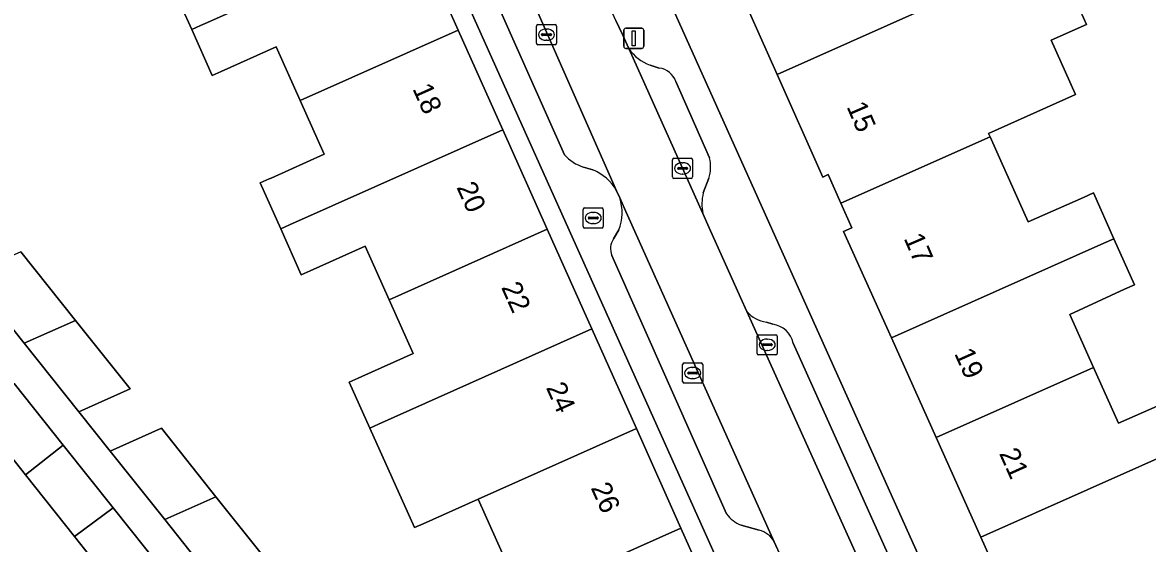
# Model space of a CAD drawing. Extents: x 163147 to 163550, y 380933 to 381639.
# Drawn here: x 163249.5 to 163305.4, y 381171.6 to 381197.5 of the extents above; entities that cross this region are included whole.
import ezdxf

# ---------------------------------------------------------------- set-up
doc = ezdxf.new("R2010")
doc.units = 0
for name, color, linetype in [('IMGEO_Brandkraan', 7, 'Continuous'), ('IMGEO_Erf', 7, 'Continuous'), ('IMGEO_Kolk', 7, 'Continuous'), ('IMGEO_Lichtmast', 7, 'Continuous'), ('IMGEO_Pand', 7, 'Continuous'), ('IMGEO_Pand_nummerreeks', 7, 'Continuous'), ('IMGEO_Parkeervlak_open', 7, 'Continuous'), ('IMGEO_Rijbaan_lokaal_open', 7, 'Continuous'), ('IMGEO_Voetpad_open', 7, 'Continuous')]:
    doc.layers.add(name, color=color, linetype=linetype)

msp = doc.modelspace()

# ---------------------------------------------------------------- linework, layer by layer
at = {"layer": 'IMGEO_Brandkraan'}
for p, q in [((163277.371, 381187.358), (163277.371, 381188.21)), ((163277.446, 381188.284), (163278.298, 381188.284)), ((163278.372, 381188.21), (163278.372, 381187.358)), ((163277.63, 381187.778), (163277.63, 381187.79)), ((163278.068, 381187.741), (163277.67, 381187.741)), ((163277.673, 381187.827), (163278.071, 381187.827)), ((163277.859, 381188.064), (163277.884, 381188.064)), ((163278.114, 381187.79), (163278.114, 381187.778)), ((163278.298, 381187.284), (163277.446, 381187.284)), ((163277.882, 381187.504), (163277.857, 381187.504))]:
    msp.add_line(p, q, dxfattribs=at)
for points in [[(163277.371, 381187.358), (163277.371, 381188.21)], [(163277.446, 381188.284), (163278.298, 381188.284)], [(163278.372, 381188.21), (163278.372, 381187.358)], [(163278.298, 381187.284), (163277.446, 381187.284)]]:
    msp.add_lwpolyline(points, dxfattribs=at)
for centre, radius, start, end in [((163277.448, 381188.208), 0.0765, 91.552, 178.448), ((163277.448, 381188.208), 0.0765, 91.552, 178.448), ((163278.296, 381188.208), 0.0765, 1.552, 88.448), ((163278.296, 381188.208), 0.0765, 1.552, 88.448), ((163277.67, 381187.787), 0.0403, 85.8775, 175.7526), ((163277.667, 381187.777), 0.0366, 178.938, 274.7102), ((163278.071, 381187.784), 0.043, 264.8664, 352.4533), ((163278.075, 381187.789), 0.0386, 1.7309, 96.639), ((163277.448, 381187.36), 0.0765, 181.552, 268.448), ((163277.448, 381187.36), 0.0765, 181.552, 268.448), ((163278.296, 381187.36), 0.0765, 271.552, 358.448), ((163278.296, 381187.36), 0.0765, 271.552, 358.448)]:
    msp.add_arc(centre, radius, start, end, dxfattribs=at)
for centre, major_axis, ratio, start_param, end_param in [((163277.858, 381187.784), (-0.387, 0.002), 0.722429, 4.712389, 7.853982), ((163277.883, 381187.784), (-0.39, 0.002), 0.717154, 1.570796, 4.712389)]:
    msp.add_ellipse(centre, major_axis=major_axis, ratio=ratio, start_param=start_param, end_param=end_param, dxfattribs=at)
at = {"layer": 'IMGEO_Erf'}
for points in [[(163270.156, 381224.203), (163305.202, 381146.131), (163304.985, 381145.89), (163307.687, 381144.941)], [(163249.445, 381186.105), (163252.159, 381182.695), (163254.871, 381179.287), (163252.323, 381178.149), (163253.099, 381177.174), (163253.874, 381176.2), (163256.422, 381177.338), (163259.133, 381173.931), (163261.845, 381170.523), (163259.298, 381169.386), (163260.074, 381168.411), (163260.866, 381167.416), (163263.413, 381168.553), (163266.107, 381165.167), (163268.685, 381161.928), (163266.571, 381160.249), (163267.347, 381159.274), (163282.659, 381139.767), (163292.918, 381150.971), (163261.531, 381220.959)], [(163268.958, 381202.078), (163271.17, 381197.125), (163273.381, 381192.174), (163275.592, 381187.222), (163277.802, 381182.271), (163280.014, 381177.318), (163282.224, 381172.367), (163284.436, 381167.414)], [(163300.743, 381201.067), (163302.37, 381197.403), (163300.616, 381196.616), (163301.823, 381193.924), (163297.507, 381191.987), (163297.586, 381191.811), (163298.121, 381190.618), (163299.481, 381187.587), (163302.222, 381188.807), (163302.722, 381189.029), (163303.738, 381186.745), (163304.755, 381184.461), (163304.269, 381184.245), (163301.543, 381182.991), (163302.725, 381180.356), (163303.971, 381177.58), (163306.712, 381178.8)], [(163264.607, 381120.389), (163281.562, 381138.569), (163278.275, 381142.629), (163276.479, 381141.205), (163274.017, 381144.311), (163273.373, 381145.124), (163271.555, 381147.417), (163269.093, 381150.523), (163266.667, 381153.583), (163264.241, 381156.644), (163261.814, 381159.705), (163259.391, 381162.762), (163256.967, 381165.819), (163254.544, 381168.876), (163252.108, 381171.949), (163249.676, 381175.016), (163247.243, 381178.086), (163244.815, 381181.148), (163242.387, 381184.211), (163239.96, 381187.273), (163237.536, 381190.33), (163235.112, 381193.388), (163232.688, 381196.445), (163230.267, 381199.5)], [(163273.352, 381171.141), (163272.16, 381173.81), (163269.42, 381172.587), (163268.988, 381172.394), (163266.775, 381177.345), (163265.755, 381179.628), (163266.19, 381179.822), (163266.375, 381179.904), (163268.93, 381181.045), (163267.738, 381183.714), (163266.546, 381186.383), (163263.807, 381185.16), (163263.37, 381184.965), (163262.35, 381187.246), (163261.33, 381189.529), (163261.769, 381189.725), (163261.872, 381189.771), (163264.508, 381190.949), (163263.316, 381193.617), (163262.124, 381196.287), (163259.385, 381195.063), (163258.945, 381194.866), (163257.925, 381197.149), (163256.904, 381199.431)], [(163306.015, 381152.115), (163303.793, 381157.068), (163301.571, 381162.02), (163299.349, 381166.972), (163297.126, 381171.926), (163294.905, 381176.877), (163292.684, 381181.828), (163290.312, 381187.114), (163290.722, 381187.298), (163290.18, 381188.516), (163289.547, 381189.939), (163289.272, 381189.817), (163287.005, 381194.915), (163284.8, 381199.874)]]:
    msp.add_lwpolyline(points, dxfattribs=at)
at = {"layer": 'IMGEO_Kolk'}
for p, q in [((163275.05, 381196.471), (163275.05, 381197.323)), ((163275.125, 381197.397), (163275.977, 381197.397)), ((163275.538, 381197.177), (163275.563, 381197.177)), ((163276.051, 381197.323), (163276.051, 381196.471)), ((163275.309, 381196.891), (163275.309, 381196.903)), ((163275.747, 381196.854), (163275.349, 381196.854)), ((163275.352, 381196.94), (163275.75, 381196.94)), ((163275.561, 381196.617), (163275.536, 381196.617)), ((163275.793, 381196.903), (163275.793, 381196.891)), ((163275.977, 381196.397), (163275.125, 381196.397)), ((163281.81, 381189.824), (163281.81, 381190.676)), ((163281.885, 381190.75), (163282.737, 381190.75)), ((163282.298, 381190.53), (163282.323, 381190.53)), ((163282.811, 381190.676), (163282.811, 381189.824)), ((163282.069, 381190.244), (163282.069, 381190.256)), ((163282.507, 381190.207), (163282.109, 381190.207)), ((163282.112, 381190.293), (163282.51, 381190.293)), ((163282.321, 381189.97), (163282.296, 381189.97)), ((163282.553, 381190.256), (163282.553, 381190.244)), ((163282.737, 381189.75), (163281.885, 381189.75)), ((163286.015, 381181.057), (163286.015, 381181.909)), ((163286.09, 381181.983), (163286.942, 381181.983)), ((163286.274, 381181.477), (163286.274, 381181.489)), ((163286.317, 381181.526), (163286.715, 381181.526)), ((163286.503, 381181.763), (163286.528, 381181.763)), ((163286.758, 381181.489), (163286.758, 381181.477)), ((163287.016, 381181.909), (163287.016, 381181.057)), ((163286.942, 381180.983), (163286.09, 381180.983)), ((163286.712, 381181.44), (163286.314, 381181.44)), ((163286.526, 381181.203), (163286.501, 381181.203)), ((163282.313, 381179.653), (163282.313, 381180.505)), ((163282.388, 381180.579), (163283.24, 381180.579)), ((163283.314, 381180.505), (163283.314, 381179.653)), ((163282.572, 381180.073), (163282.572, 381180.085)), ((163283.01, 381180.036), (163282.612, 381180.036)), ((163282.615, 381180.122), (163283.013, 381180.122)), ((163282.801, 381180.359), (163282.826, 381180.359)), ((163283.056, 381180.085), (163283.056, 381180.073)), ((163283.24, 381179.579), (163282.388, 381179.579)), ((163282.824, 381179.799), (163282.799, 381179.799))]:
    msp.add_line(p, q, dxfattribs=at)
for points in [[(163275.05, 381196.471), (163275.05, 381197.323)], [(163275.125, 381197.397), (163275.977, 381197.397)], [(163276.051, 381197.323), (163276.051, 381196.471)], [(163275.977, 381196.397), (163275.125, 381196.397)], [(163281.81, 381189.824), (163281.81, 381190.676)], [(163281.885, 381190.75), (163282.737, 381190.75)], [(163282.811, 381190.676), (163282.811, 381189.824)], [(163282.737, 381189.75), (163281.885, 381189.75)], [(163286.015, 381181.057), (163286.015, 381181.909)], [(163286.09, 381181.983), (163286.942, 381181.983)], [(163287.016, 381181.909), (163287.016, 381181.057)], [(163286.942, 381180.983), (163286.09, 381180.983)], [(163282.313, 381179.653), (163282.313, 381180.505)], [(163282.388, 381180.579), (163283.24, 381180.579)], [(163283.314, 381180.505), (163283.314, 381179.653)], [(163283.24, 381179.579), (163282.388, 381179.579)]]:
    msp.add_lwpolyline(points, dxfattribs=at)
for centre, radius, start, end in [((163275.127, 381197.321), 0.0765, 91.552, 178.448), ((163275.127, 381197.321), 0.0765, 91.552, 178.448), ((163275.975, 381197.321), 0.0765, 1.552, 88.448), ((163275.975, 381197.321), 0.0765, 1.552, 88.448), ((163275.349, 381196.9), 0.0403, 85.8775, 175.7526), ((163275.346, 381196.89), 0.0366, 178.938, 274.7102), ((163275.75, 381196.897), 0.043, 264.8664, 352.4533), ((163275.754, 381196.902), 0.0386, 1.7309, 96.639), ((163275.127, 381196.473), 0.0765, 181.552, 268.448), ((163275.127, 381196.473), 0.0765, 181.552, 268.448), ((163275.975, 381196.473), 0.0765, 271.552, 358.448), ((163275.975, 381196.473), 0.0765, 271.552, 358.448), ((163281.887, 381190.674), 0.0765, 91.552, 178.448), ((163281.887, 381190.674), 0.0765, 91.552, 178.448), ((163282.735, 381190.674), 0.0765, 1.552, 88.448), ((163282.735, 381190.674), 0.0765, 1.552, 88.448), ((163282.109, 381190.253), 0.0403, 85.8775, 175.7526), ((163282.106, 381190.243), 0.0366, 178.938, 274.7102), ((163282.51, 381190.25), 0.043, 264.8664, 352.4533), ((163282.514, 381190.255), 0.0386, 1.7309, 96.639), ((163281.887, 381189.826), 0.0765, 181.552, 268.448), ((163281.887, 381189.826), 0.0765, 181.552, 268.448), ((163282.735, 381189.826), 0.0765, 271.552, 358.448), ((163282.735, 381189.826), 0.0765, 271.552, 358.448), ((163286.092, 381181.907), 0.0765, 91.552, 178.448), ((163286.092, 381181.907), 0.0765, 91.552, 178.448), ((163286.314, 381181.486), 0.0403, 85.8775, 175.7526), ((163286.719, 381181.488), 0.0386, 1.7309, 96.639), ((163286.94, 381181.907), 0.0765, 1.552, 88.448), ((163286.94, 381181.907), 0.0765, 1.552, 88.448), ((163286.092, 381181.059), 0.0765, 181.552, 268.448), ((163286.092, 381181.059), 0.0765, 181.552, 268.448), ((163286.311, 381181.476), 0.0366, 178.938, 274.7102), ((163286.715, 381181.483), 0.043, 264.8664, 352.4533), ((163286.94, 381181.059), 0.0765, 271.552, 358.448), ((163286.94, 381181.059), 0.0765, 271.552, 358.448), ((163282.39, 381180.503), 0.0765, 91.552, 178.448), ((163282.39, 381180.503), 0.0765, 91.552, 178.448), ((163283.238, 381180.503), 0.0765, 1.552, 88.448), ((163283.238, 381180.503), 0.0765, 1.552, 88.448), ((163282.612, 381180.082), 0.0403, 85.8775, 175.7526), ((163282.609, 381180.072), 0.0366, 178.938, 274.7102), ((163283.013, 381180.079), 0.043, 264.8664, 352.4533), ((163283.017, 381180.084), 0.0386, 1.7309, 96.639), ((163282.39, 381179.655), 0.0765, 181.552, 268.448), ((163282.39, 381179.655), 0.0765, 181.552, 268.448), ((163283.238, 381179.655), 0.0765, 271.552, 358.448), ((163283.238, 381179.655), 0.0765, 271.552, 358.448)]:
    msp.add_arc(centre, radius, start, end, dxfattribs=at)
for centre, major_axis, ratio, start_param, end_param in [((163275.537, 381196.897), (-0.387, 0.002), 0.722429, 4.712389, 7.853982), ((163275.562, 381196.897), (-0.39, 0.002), 0.717154, 1.570796, 4.712389), ((163282.297, 381190.25), (-0.387, 0.002), 0.722429, 4.712389, 7.853982), ((163282.322, 381190.25), (-0.39, 0.002), 0.717154, 1.570796, 4.712389), ((163286.502, 381181.483), (-0.387, 0.002), 0.722429, 4.712389, 7.853982), ((163286.527, 381181.483), (-0.39, 0.002), 0.717154, 1.570796, 4.712389), ((163282.8, 381180.079), (-0.387, 0.002), 0.722429, 4.712389, 7.853982), ((163282.825, 381180.079), (-0.39, 0.002), 0.717154, 1.570796, 4.712389)]:
    msp.add_ellipse(centre, major_axis=major_axis, ratio=ratio, start_param=start_param, end_param=end_param, dxfattribs=at)
at = {"layer": 'IMGEO_Lichtmast'}
for p, q in [((163279.489, 381197.217), (163280.279, 381197.217)), ((163280.279, 381197.217), (163279.489, 381197.217)), ((163279.389, 381196.317), (163279.389, 381197.117)), ((163279.389, 381197.117), (163279.389, 381196.317)), ((163280.379, 381197.117), (163280.379, 381196.317)), ((163280.379, 381196.317), (163280.379, 381197.117)), ((163280.279, 381196.217), (163279.489, 381196.217)), ((163279.489, 381196.217), (163280.279, 381196.217))]:
    msp.add_line(p, q, dxfattribs=at)
msp.add_lwpolyline([(163279.809, 381197.092), (163279.959, 381197.092), (163279.959, 381196.342), (163279.809, 381196.342), (163279.809, 381197.092)], dxfattribs=at)
for centre, start, end in [((163279.489, 381197.117), 90, 180), ((163279.489, 381197.117), 90, 180), ((163280.279, 381197.117), 0, 90), ((163280.279, 381197.117), 360, 90), ((163279.489, 381196.317), 180, 270), ((163279.489, 381196.317), 180, 270), ((163280.279, 381196.317), 270, 0), ((163280.279, 381196.317), 270, 0)]:
    msp.add_arc(centre, 0.1, start, end, dxfattribs=at)
at = {"layer": 'IMGEO_Pand'}
for points in [[(163266.748, 381207.029), (163258.894, 381203.521), (163260.086, 381200.852), (163257.526, 381199.709), (163257.347, 381199.629), (163256.904, 381199.431), (163257.925, 381197.149), (163258.366, 381197.346), (163258.603, 381197.452), (163268.958, 381202.078)], [(163297.934, 381199.81), (163296.92, 381202.094), (163293.795, 381200.695), (163292.616, 381203.351), (163284.8, 381199.874), (163287.005, 381194.915)], [(163268.958, 381202.078), (163258.603, 381197.452), (163258.366, 381197.346), (163257.925, 381197.149), (163258.945, 381194.866), (163259.385, 381195.063), (163262.124, 381196.287), (163263.316, 381193.617), (163271.17, 381197.125)], [(163290.18, 381188.516), (163297.586, 381191.811), (163297.507, 381191.987), (163301.823, 381193.924), (163300.616, 381196.616), (163302.37, 381197.403), (163300.743, 381201.067), (163297.934, 381199.81), (163287.005, 381194.915), (163289.272, 381189.817), (163289.547, 381189.939)], [(163271.17, 381197.125), (163263.316, 381193.617), (163264.508, 381190.949), (163261.872, 381189.771), (163261.769, 381189.725), (163261.33, 381189.529), (163262.35, 381187.246), (163262.788, 381187.442), (163273.381, 381192.174)], [(163273.381, 381192.174), (163262.788, 381187.442), (163262.35, 381187.246), (163263.37, 381184.965), (163263.807, 381185.16), (163266.546, 381186.383), (163267.738, 381183.714), (163275.592, 381187.222)], [(163298.121, 381190.618), (163297.586, 381191.811), (163290.18, 381188.516), (163290.722, 381187.298), (163290.312, 381187.114), (163292.684, 381181.828), (163303.245, 381186.526), (163303.738, 381186.745), (163302.722, 381189.029), (163302.222, 381188.807), (163299.481, 381187.587)], [(163275.592, 381187.222), (163267.738, 381183.714), (163268.93, 381181.045), (163266.375, 381179.904), (163266.19, 381179.822), (163265.755, 381179.628), (163266.775, 381177.345), (163267.21, 381177.539), (163277.802, 381182.271)], [(163301.543, 381182.991), (163304.269, 381184.245), (163304.755, 381184.461), (163303.738, 381186.745), (163303.245, 381186.526), (163292.684, 381181.828), (163294.905, 381176.877), (163302.725, 381180.356)], [(163246.895, 381184.967), (163249.61, 381181.556), (163252.159, 381182.695), (163249.445, 381186.105)], [(163252.159, 381182.695), (163249.61, 381181.556), (163252.323, 381178.149), (163254.871, 381179.287)], [(163280.014, 381177.318), (163277.802, 381182.271), (163267.21, 381177.539), (163266.775, 381177.345), (163268.988, 381172.394), (163269.42, 381172.587), (163272.16, 381173.81)], [(163308.15, 381176.83), (163307.181, 381179.008), (163306.712, 381178.8), (163303.971, 381177.58), (163302.725, 381180.356), (163294.905, 381176.877), (163297.126, 381171.926), (163307.688, 381176.624)], [(163247.243, 381178.086), (163249.676, 381175.016), (163251.545, 381176.497), (163249.108, 381179.565)], [(163253.874, 381176.2), (163256.586, 381172.793), (163259.133, 381173.931), (163256.422, 381177.338)], [(163280.014, 381177.318), (163272.16, 381173.81), (163273.352, 381171.141), (163270.612, 381169.918), (163270.18, 381169.725), (163271.201, 381167.442), (163271.632, 381167.635), (163271.758, 381167.691), (163282.224, 381172.367)], [(163252.108, 381171.949), (163254.017, 381173.386), (163251.545, 381176.497), (163249.676, 381175.016)], [(163305.97, 381173.124), (163308.711, 381174.343), (163309.167, 381174.546), (163308.15, 381176.83), (163307.688, 381176.624), (163297.126, 381171.926), (163299.349, 381166.972), (163307.17, 381170.451)], [(163259.133, 381173.931), (163256.586, 381172.793), (163259.298, 381169.386), (163261.845, 381170.523)], [(163254.544, 381168.876), (163256.419, 381170.362), (163254.017, 381173.386), (163252.108, 381171.949)], [(163282.224, 381172.367), (163271.758, 381167.691), (163271.632, 381167.635), (163271.201, 381167.442), (163273.413, 381162.491), (163273.538, 381162.547), (163276.582, 381163.906), (163284.436, 381167.414)]]:
    msp.add_lwpolyline(points, close=True, dxfattribs=at)
at = {"layer": 'IMGEO_Parkeervlak_open'}
for points in [[(163265.069, 381216.59), (163266.264, 381213.829), (163276.442, 381190.926)], [(163279.033, 381189.142), (163278.853, 381189.551), (163267.981, 381214.197)], [(163279.639, 381196.203), (163283.317, 381188.009)], [(163281.154, 381195.239), (163280.697, 381195.382)], [(163283.656, 381190.771), (163281.982, 381194.567)], [(163277.394, 381190.316), (163277.847, 381190.174)], [(163283.342, 381189.03), (163283.616, 381189.756)], [(163279.421, 381188.263), (163279.191, 381188.785)], [(163286.858, 381171.695), (163279.421, 381188.263)], [(163279.15, 381187.192), (163278.878, 381186.745)], [(163278.799, 381185.924), (163284.501, 381173.079)], [(163285.499, 381183.144), (163298.58, 381154.093)], [(163286.794, 381182.499), (163286.478, 381182.605)], [(163299.045, 381156.535), (163287.809, 381181.57)], [(163285.221, 381172.518), (163286.122, 381172.264)]]:
    msp.add_lwpolyline(points, dxfattribs=at)
for centre, radius, start, end in [((163281.432, 381197.422), 2.168, 214.1986, 250.1791), ((163280.986, 381194.186), 1.066, 20.9306, 80.9443), ((163278.054, 381192.394), 2.181, 222.3245, 252.3755), ((163281.615, 381190.343), 2.086, 343.6502, 11.8362), ((163276.989, 381187.99), 2.346, 29.3986, 68.545), ((163276.953, 381188.046), 2.357, 338.7658, 18.2856), ((163285.553, 381188.465), 2.282, 165.6663, 191.5284), ((163279.585, 381186.263), 0.856, 145.7001, 203.3072), ((163286.717, 381184.198), 1.611, 220.8637, 261.4653), ((163286.65, 381181.323), 1.185, 12.0468, 83.0192), ((163285.715, 381173.895), 1.462, 213.8922, 250.2587), ((163285.831, 381171.127), 1.174, 28.9511, 75.6339)]:
    msp.add_arc(centre, radius, start, end, dxfattribs=at)
at = {"layer": 'IMGEO_Rijbaan_lokaal_open'}
for points in [[(163279.639, 381196.203), (163279.327, 381196.899), (163279.003, 381197.607), (163270.799, 381215.542), (163268.013, 381221.744)], [(163265.292, 381220.107), (163265.579, 381219.475), (163266, 381218.425), (163267.981, 381214.197), (163278.853, 381189.551), (163279.033, 381189.142), (163279.191, 381188.785), (163279.421, 381188.263), (163286.858, 381171.695), (163287.205, 381170.923), (163295.412, 381152.683), (163298.58, 381154.093), (163285.499, 381183.144), (163285.19, 381183.834), (163283.635, 381187.3), (163283.317, 381188.009), (163279.639, 381196.203)]]:
    msp.add_lwpolyline(points, dxfattribs=at)
at = {"layer": 'IMGEO_Voetpad_open'}
for points in [[(163295.382, 381136.166), (163304.985, 381145.89), (163305.202, 381146.131), (163270.156, 381224.203), (163267.96, 381228.115), (163267.915, 381228.196), (163266.853, 381229.481), (163266.785, 381229.563), (163249.895, 381250)], [(163242.336, 381248.283), (163240.64, 381246.663), (163260.513, 381222.504), (163261.531, 381220.959), (163292.918, 381150.971), (163282.659, 381139.767), (163281.562, 381138.569), (163264.607, 381120.389), (163267.528, 381117.294), (163268.925, 381118.765), (163274.405, 381124.631), (163277.004, 381127.456)], [(163276.442, 381190.926), (163266.264, 381213.829), (163265.069, 381216.59)], [(163279.003, 381197.607), (163279.327, 381196.899), (163279.639, 381196.203)], [(163280.697, 381195.382), (163281.154, 381195.239)], [(163281.982, 381194.567), (163283.656, 381190.771)], [(163277.847, 381190.174), (163277.394, 381190.316)], [(163283.616, 381189.756), (163283.342, 381189.03)], [(163279.191, 381188.785), (163279.033, 381189.142)], [(163283.317, 381188.009), (163283.635, 381187.3), (163285.19, 381183.834), (163285.499, 381183.144)], [(163278.878, 381186.745), (163279.15, 381187.192)], [(163284.501, 381173.079), (163278.799, 381185.924)], [(163259.298, 381169.386), (163256.586, 381172.793), (163253.874, 381176.2), (163253.099, 381177.174), (163252.323, 381178.149), (163249.61, 381181.556), (163246.895, 381184.967)], [(163286.478, 381182.605), (163286.794, 381182.499)], [(163287.809, 381181.57), (163299.045, 381156.535)], [(163249.108, 381179.565), (163251.545, 381176.497), (163254.017, 381173.386), (163256.419, 381170.362)], [(163286.122, 381172.264), (163285.221, 381172.518)], [(163287.205, 381170.923), (163286.858, 381171.695)]]:
    msp.add_lwpolyline(points, dxfattribs=at)
for centre, radius, start, end in [((163281.432, 381197.422), 2.168, 214.1986, 250.1791), ((163280.986, 381194.186), 1.066, 20.9306, 80.9443), ((163278.054, 381192.394), 2.181, 222.3245, 252.3755), ((163281.615, 381190.343), 2.086, 343.6502, 11.8362), ((163276.989, 381187.99), 2.346, 29.3986, 68.545), ((163276.953, 381188.046), 2.357, 338.7658, 18.2856), ((163285.553, 381188.465), 2.282, 165.6663, 191.5284), ((163279.585, 381186.263), 0.856, 145.7001, 203.3072), ((163286.717, 381184.198), 1.611, 220.8637, 261.4653), ((163286.65, 381181.323), 1.185, 12.0468, 83.0192), ((163285.715, 381173.895), 1.462, 213.8922, 250.2587), ((163285.831, 381171.127), 1.174, 28.9511, 75.6339)]:
    msp.add_arc(centre, radius, start, end, dxfattribs=at)

# ---------------------------------------------------------------- texts
at = {"layer": 'IMGEO_Pand_nummerreeks'}
for s, rotation, p in [('18', 294.0583, (163268.879, 381194.213)), ('15', 293.4558, (163290.444, 381193.32)), ('20', 294.0583, (163271.066, 381189.315)), ('17', 293.4567, (163293.284, 381186.777)), ('22', 294.0583, (163273.286, 381184.34)), ('19', 294.1614, (163295.792, 381181.054)), ('24', 294.0583, (163275.512, 381179.357)), ('21', 294.1614, (163298.023, 381176.083)), ('26', 294.0583, (163277.736, 381174.376))]:
    msp.add_text(s, height=1, rotation=rotation, dxfattribs=at).set_placement(p)

doc.saveas('drawing.dxf')
